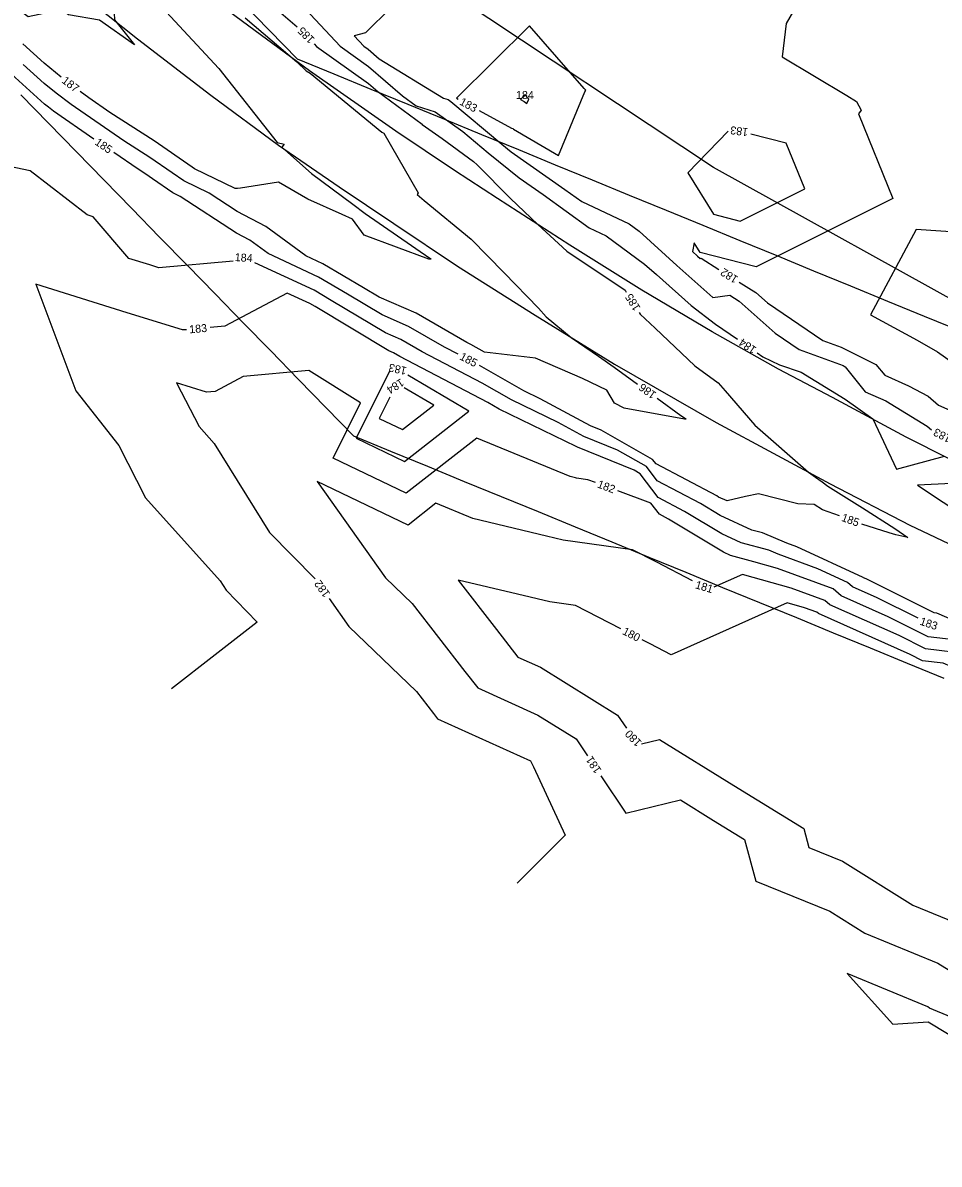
# Model space of a CAD drawing. Extents: x 2086416 to 2115205, y 575507 to 632762.
# Drawn here: x 2110459.9 to 2110689, y 581574.2 to 581859.5 of the extents above; entities that cross this region are included whole.
import ezdxf

# ---------------------------------------------------------------- set-up
doc = ezdxf.new("R2010")
doc.units = 0
for name, color, linetype in [('DTM Contours Major', 7, 'Continuous'), ('DTM Contours Major Text', 7, 'Continuous'), ('DTM Contours Minor', 7, 'Continuous'), ('DTM Contours Minor Text', 7, 'Continuous'), ('Exist Hydrographic FEMA Cross Section', 7, 'Continuous'), ('Exist Roads EOP', 7, 'Continuous'), ('Exist Vegetation Woods Line', 7, 'Continuous')]:
    doc.layers.add(name, color=color, linetype=linetype)

msp = doc.modelspace()

# ---------------------------------------------------------------- linework, layer by layer
at = {"layer": 'DTM Contours Major'}
for points in [[(2110457, 581927.88), (2110460.22, 581924.41), (2110465.69, 581919.7), (2110467.09, 581918.26), (2110471.2, 581912.48), (2110474.08, 581909.72), (2110478.74, 581904.23), (2110484.88, 581896.98), (2110489.67, 581891.41), (2110497.24, 581885.1), (2110503.54, 581879.8), (2110508.99, 581875.69), (2110517.48, 581867.91), (2110520.9, 581865), (2110528.46, 581858.48)], [(2110477.66, 581830.47), (2110467.52, 581837.44), (2110466.26, 581838.39), (2110465.28, 581839.19), (2110446.86, 581855.82), (2110445.45, 581856.9), (2110444.68, 581857.31), (2110425.22, 581874.31), (2110424.26, 581875.03), (2110421.59, 581877.72), (2110420.54, 581878.96), (2110417.81, 581883.75), (2110405.43, 581897.24), (2110404.4, 581897.68)], [(2110532.7, 581854.24), (2110533.29, 581853.61), (2110546.33, 581844.33), (2110548.63, 581842.34), (2110559.7, 581834.14), (2110559.75, 581834.13), (2110564.69, 581830.63), (2110572.56, 581824.83), (2110573.43, 581823.98), (2110581.79, 581815.57), (2110588.65, 581809.09), (2110593.79, 581804.33), (2110595.84, 581802.4), (2110610.44, 581792.71), (2110610.75, 581792.22)], [(2110568.71, 581776.67), (2110565.29, 581778.46), (2110556.33, 581783.64), (2110549.74, 581786.49), (2110541.03, 581791.71), (2110533.8, 581795.96), (2110521.17, 581801.83), (2110516.59, 581805.2), (2110513.26, 581806.95), (2110499.23, 581816.12), (2110497.37, 581817.02), (2110492.3, 581820.5), (2110490.63, 581821.65), (2110488.68, 581822.91), (2110482.6, 581827.08)], [(2110613.93, 581787.13), (2110614.2, 581786.7), (2110617.97, 581783.15), (2110627.86, 581773.78), (2110633.68, 581769.53), (2110635.48, 581767.5), (2110642.91, 581758.9), (2110656.28, 581747.21), (2110658.07, 581745.98), (2110659.68, 581744.77), (2110661.17, 581743.69), (2110669.84, 581738.28), (2110677.86, 581733.15), (2110681.1, 581730.87), (2110678.11, 581731.54), (2110676.51, 581732.02), (2110669.66, 581734.22)], [(2110664.02, 581736.26), (2110659.78, 581737.81), (2110657.7, 581739.14), (2110653.61, 581739.28), (2110643.82, 581741.77), (2110640.51, 581741.07), (2110635.97, 581739.99), (2110633.83, 581740.98), (2110633.38, 581741.25), (2110618.18, 581749.26), (2110617.34, 581750.37), (2110604.48, 581757.66), (2110601.81, 581758.74), (2110589.19, 581765.53), (2110585.16, 581767.49), (2110574.02, 581773.87)], [(2110609.4, 581708.01), (2110598.08, 581713.85), (2110591.61, 581714.75), (2110583.58, 581716.66), (2110568.72, 581720.2), (2110578.29, 581707.88), (2110583.65, 581700.97), (2110589.26, 581698.44), (2110608.58, 581686.48), (2110610.79, 581683.18)], [(2110706.28, 581691.93), (2110693.8, 581697.81), (2110690.01, 581699.43), (2110684.82, 581700.07), (2110681.7, 581701.62), (2110658.82, 581711.83), (2110658.38, 581712.2), (2110655.34, 581713.32), (2110650.98, 581714.55), (2110621.94, 581701.5), (2110616.68, 581704.25), (2110614.73, 581705.26)], [(2110614.54, 581679.26), (2110619.08, 581680.34), (2110637.66, 581668.88), (2110655.14, 581658.09), (2110656.42, 581653.38), (2110664.82, 581649.96), (2110682.42, 581638.95), (2110691.1, 581635.36), (2110698.64, 581630.7)]]:
    msp.add_lwpolyline(points, dxfattribs=at)
at = {"layer": 'DTM Contours Minor'}
for points in [[(2110672.37, 581932.97), (2110662.96, 581880.6), (2110650.69, 581859.37), (2110649.72, 581851), (2110665.85, 581841.38), (2110668.3, 581839.83), (2110669.46, 581837.68), (2110668.83, 581836.73), (2110677.42, 581815.61), (2110643.22, 581798.5), (2110629.19, 581802.12), (2110627.72, 581804.48), (2110627.29, 581802.33), (2110628.54, 581801.21), (2110629.18, 581800.63), (2110629.48, 581800.67), (2110633.9, 581797.89)], [(2110450.53, 581896.22), (2110460.85, 581885.58), (2110470.34, 581875.69), (2110478.68, 581867.9), (2110482.59, 581863.61), (2110482.79, 581860.24), (2110487.75, 581854.01), (2110479.08, 581860.14), (2110471.27, 581861.55), (2110469.42, 581862.78), (2110461.2, 581860.98), (2110453.09, 581866.98)], [(2110558.34, 581869.72), (2110545.52, 581856.99), (2110542.75, 581856.27), (2110545.16, 581853.69), (2110546.22, 581852.94), (2110548.99, 581850.55), (2110565.08, 581840.7), (2110566.2, 581840.35), (2110566.87, 581839.88), (2110579.59, 581829.15), (2110581.96, 581827.24), (2110595.34, 581817.89), (2110599.61, 581814.81), (2110611.44, 581809.26), (2110613.94, 581807.43), (2110623.41, 581798.89), (2110632.4, 581790.87), (2110636.67, 581791.41), (2110638.99, 581789.95), (2110647.93, 581781.91), (2110653.98, 581777.82), (2110665, 581773.88), (2110665.48, 581773.5), (2110670.48, 581767.29), (2110675.64, 581765.02), (2110686.01, 581758.67), (2110687.06, 581757.75)], [(2110529.31, 581864.26), (2110539.23, 581853.65), (2110546.28, 581848.63), (2110554.8, 581841.28), (2110558.25, 581838.73), (2110562.98, 581837.24), (2110569.88, 581832.35), (2110576.18, 581827.04), (2110583.95, 581820.79), (2110589.99, 581816.57), (2110601.5, 581808.27), (2110605.72, 581806.3), (2110615.34, 581799.22), (2110618.29, 581796.57), (2110626.94, 581788.84), (2110633.04, 581784.18), (2110638.55, 581780.4)], [(2110495.74, 581862.22), (2110508.87, 581848.12), (2110523.46, 581829.63), (2110525.22, 581829.21), (2110524.61, 581828.41), (2110532.08, 581821.86), (2110542.36, 581814.17), (2110545.49, 581811.81), (2110561.59, 581800.7), (2110561.76, 581800.58), (2110561.98, 581800.42), (2110561.7, 581800.45), (2110561.38, 581800.45), (2110545.25, 581806.45), (2110542.27, 581810.4), (2110539.71, 581811.6), (2110531.09, 581815.45), (2110523.77, 581819.71), (2110514.3, 581818.22), (2110513.57, 581818.12), (2110512.97, 581818.09), (2110502.82, 581823.01), (2110502.17, 581823.46), (2110492.67, 581829.99), (2110481.59, 581837.13), (2110476.34, 581840.73), (2110474.24, 581842.32)], [(2110515.46, 581860.72), (2110528.41, 581849.79), (2110530.67, 581847.54), (2110531.75, 581846.95), (2110549.59, 581832.22), (2110550.09, 581831.92), (2110558.68, 581817.04), (2110558.5, 581816.59), (2110559.05, 581816.07), (2110560.19, 581815.06), (2110571.99, 581805.45), (2110580.21, 581797), (2110588.8, 581788.18), (2110590.74, 581785.98), (2110597, 581780.84), (2110603.79, 581776.21), (2110607.72, 581773.43), (2110613.57, 581769.21)], [(2110600.23, 581843.07), (2110586.52, 581858.73), (2110568.37, 581840.76), (2110568.26, 581840.65), (2110568.7, 581840.41)], [(2110469.47, 581845.96), (2110465.2, 581849.45), (2110459.85, 581854.28)], [(2110618.43, 581765.7), (2110624.41, 581761.39), (2110625.53, 581760.59), (2110625.71, 581760.46), (2110625.57, 581760.44), (2110625.32, 581760.46), (2110610.18, 581763.16), (2110607.84, 581764.48), (2110605.89, 581767.69), (2110599.83, 581770.6), (2110588.05, 581775.67), (2110575.32, 581777.15), (2110571.92, 581779.1), (2110570.88, 581779.64), (2110558.23, 581786.95), (2110548.94, 581790.97), (2110545.08, 581793.28), (2110534.9, 581799.26), (2110530.6, 581801.26), (2110520.65, 581808.56), (2110513.43, 581812.38), (2110506.49, 581816.91), (2110500.09, 581820.02), (2110497.24, 581821.98), (2110491.65, 581825.82), (2110485.13, 581830.02), (2110471.93, 581839.08), (2110468.18, 581841.92), (2110465.24, 581844.32), (2110459.93, 581849.12)], [(2110573.98, 581837.56), (2110582.06, 581833.21), (2110582.34, 581833.06), (2110582.57, 581832.93), (2110593.83, 581826.33), (2110600.42, 581842.24), (2110600.59, 581842.66), (2110600.23, 581843.07)], [(2110585.45, 581841.47), (2110584.27, 581840.31), (2110585.18, 581839.82), (2110585.92, 581839.38), (2110586.35, 581840.44), (2110585.45, 581841.47)], [(2110636.25, 581832.4), (2110626.11, 581822.05), (2110632.59, 581811.67), (2110639.22, 581809.96)], [(2110639.22, 581809.96), (2110655.4, 581818.04), (2110650.75, 581829.46), (2110641.86, 581831.69)], [(2110512.45, 581799.94), (2110493.85, 581798.28), (2110491.61, 581798.98), (2110486.39, 581800.61), (2110477.44, 581810.98), (2110475.99, 581811.48), (2110461.73, 581822.53), (2110445.25, 581825.89), (2110436.87, 581830.21), (2110421.03, 581830.82), (2110422.59, 581804.61), (2110419.24, 581796.01), (2110417.96, 581786.65), (2110435.66, 581768.75), (2110437.3, 581769.68), (2110441.51, 581762.84), (2110427.74, 581762.65), (2110429.81, 581758.8)], [(2110699.21, 581806.73), (2110683.26, 581807.82), (2110671.77, 581786.48), (2110683.44, 581780.2), (2110688.54, 581777.3), (2110700.9, 581768.53), (2110709.47, 581765.13), (2110714.47, 581763.07)], [(2110695.32, 581708.96), (2110688.38, 581711.98), (2110687.7, 581712.06), (2110670.71, 581720.49), (2110670.08, 581720.77), (2110669.96, 581720.88), (2110653.37, 581728.55), (2110650.87, 581729.48), (2110644.8, 581731.99), (2110642.12, 581732.73), (2110634.23, 581736.4), (2110629.34, 581739.32), (2110618.45, 581745.06), (2110615.77, 581748.59), (2110608.58, 581752.66), (2110600.16, 581756.1), (2110593.72, 581759.57), (2110582.07, 581765.24), (2110574.71, 581769.45), (2110559.71, 581777.28), (2110554.42, 581780.33), (2110550.55, 581782.01), (2110536.98, 581790.14), (2110532.7, 581792.66), (2110517.86, 581799.55)], [(2110500.75, 581782.81), (2110499.83, 581782.73), (2110485.95, 581787.05), (2110463.09, 581794.19), (2110473.14, 581767.52), (2110483.87, 581753.84), (2110490.58, 581740.81), (2110509.23, 581720), (2110510.69, 581717.66), (2110518.48, 581709.68), (2110507.93, 581701.5), (2110497.05, 581693.06)], [(2110638.98, 581794.7), (2110643.14, 581792.08), (2110646.01, 581789.5), (2110659.86, 581780.13), (2110664.5, 581778.47), (2110673.17, 581774.14), (2110675.37, 581771.42), (2110681.32, 581768.8), (2110686.2, 581766.18), (2110688.77, 581763.93), (2110698.41, 581759.72)], [(2110683.75, 581710.67), (2110673.46, 581715.77), (2110667.27, 581718.53), (2110666.02, 581719.6), (2110658.64, 581723.02), (2110648.68, 581726.7), (2110646.35, 581727.67), (2110639.48, 581729.56), (2110634.63, 581731.81), (2110625.3, 581737.4), (2110618.73, 581740.86), (2110614.2, 581746.81), (2110612.68, 581747.67), (2110598.52, 581753.46), (2110598.25, 581753.6), (2110578.98, 581762.98), (2110576.1, 581764.63), (2110554.12, 581776.1), (2110552.52, 581777.02), (2110551.35, 581777.53), (2110532.93, 581788.57), (2110531.59, 581789.36), (2110525.98, 581791.96), (2110510.37, 581783.67), (2110506.73, 581783.34)], [(2110643.49, 581777), (2110644.91, 581776.03), (2110649.04, 581774.01), (2110654.46, 581772.18), (2110665.46, 581765.46), (2110672.35, 581760.51), (2110678.29, 581747.94), (2110690.29, 581751.21)], [(2110603.01, 581744.61), (2110601.15, 581745.31), (2110598.31, 581745.71), (2110598.02, 581745.77), (2110596.73, 581746.08), (2110573.36, 581755.71), (2110555.74, 581741.92), (2110537.44, 581750.71), (2110544.33, 581764.55), (2110531.39, 581772.62), (2110514.95, 581771.08), (2110507.97, 581767.37), (2110505.82, 581767.18), (2110498.31, 581769.52), (2110503.93, 581758.61), (2110507.74, 581754.35), (2110521.55, 581732.14), (2110532.92, 581720.5)], [(2110551.55, 581772.41), (2110543.21, 581755.67), (2110555.29, 581749.87)], [(2110555.29, 581749.87), (2110571.37, 581762.46), (2110556.13, 581771.4)], [(2110551.65, 581765.96), (2110548.99, 581760.63), (2110554.83, 581757.82)], [(2110554.83, 581757.82), (2110562.62, 581763.92), (2110555.24, 581768.24)], [(2110627.31, 581720), (2110618.35, 581724.7), (2110612.34, 581727.81), (2110594.96, 581730.23), (2110590.8, 581731.21), (2110572.39, 581735.61), (2110563.15, 581739.41), (2110556.19, 581733.96), (2110533.5, 581744.86), (2110550.52, 581720.81), (2110557.19, 581714.38), (2110570.41, 581697.37), (2110573.61, 581693.25), (2110588.65, 581686.44), (2110598.2, 581680.53), (2110601.06, 581676.27)], [(2110695.55, 581744.5), (2110683.59, 581743.96), (2110696.4, 581735.45)], [(2110694.89, 581704.99), (2110686.26, 581706.07), (2110676.21, 581711.05), (2110664.45, 581716.3), (2110662.47, 581718.01), (2110648.59, 581723.13), (2110642.65, 581724.79), (2110636.84, 581726.39), (2110635.03, 581727.23), (2110621.26, 581735.48), (2110619.01, 581736.67), (2110616.91, 581739.41), (2110608.63, 581742.51)], [(2110696.5, 581701.71), (2110685.54, 581703.07), (2110678.96, 581706.34), (2110661.63, 581714.06), (2110660.42, 581715.1), (2110651.96, 581718.23), (2110639.81, 581721.63), (2110632.66, 581718.42)], [(2110536.42, 581715.62), (2110541.37, 581708.61), (2110558.26, 581692.36), (2110562.53, 581686.86), (2110563.56, 581685.53), (2110586.82, 581675), (2110587.51, 581673.53), (2110595.49, 581656.49), (2110583.43, 581644.45)], [(2110604.39, 581671.28), (2110610.61, 581661.99), (2110624.31, 581665.25), (2110632.56, 581660.16), (2110640.32, 581655.37), (2110643.15, 581644.99), (2110661.66, 581637.44), (2110670.37, 581631.99), (2110688.6, 581624.45), (2110697.54, 581618.92), (2110715.51, 581611.4), (2110724.37, 581605.97), (2110742.09, 581598.48), (2110752.98, 581596.4), (2110770.33, 581589.17), (2110775.18, 581586.24)], [(2110742.87, 581589.81), (2110740.96, 581590.18), (2110714.65, 581601.3), (2110713.6, 581601.94), (2110686.58, 581613.24), (2110686.1, 581613.54), (2110665.95, 581621.88), (2110677.38, 581609.19), (2110686.18, 581609.76), (2110710, 581595.5), (2110714.28, 581597.88), (2110733.49, 581588.34), (2110739.88, 581585.59), (2110744.53, 581584.59), (2110766.06, 581574.38), (2110767.08, 581574.21)]]:
    msp.add_lwpolyline(points, dxfattribs=at)
at = {"layer": 'Exist Hydrographic FEMA Cross Section'}
for points in [[(2110694.56, 581782.32), (2110685.33, 581786.1), (2110676.11, 581789.89), (2110666.89, 581793.68), (2110657.66, 581797.46), (2110648.43, 581801.24), (2110639.21, 581805.03), (2110629.98, 581808.82), (2110620.76, 581812.6), (2110611.53, 581816.38), (2110602.31, 581820.17), (2110593.08, 581823.95), (2110583.86, 581827.74), (2110574.63, 581831.52), (2110565.41, 581835.31), (2110556.18, 581839.09), (2110546.96, 581842.88), (2110537.73, 581846.66), (2110528.51, 581850.45), (2110521.57, 581857.56), (2110514.63, 581864.67)], [(2110690.26, 581695.61), (2110681.04, 581699.39), (2110671.81, 581703.18), (2110662.58, 581706.96), (2110653.36, 581710.75), (2110644.14, 581714.53), (2110634.91, 581718.32), (2110625.68, 581722.1), (2110616.46, 581725.89), (2110607.23, 581729.67), (2110598.01, 581733.46), (2110588.78, 581737.24), (2110579.56, 581741.02), (2110570.33, 581744.81), (2110561.11, 581748.6), (2110551.88, 581752.38), (2110542.66, 581756.16), (2110535.72, 581763.28), (2110528.78, 581770.39), (2110521.84, 581777.5), (2110514.9, 581784.61), (2110507.96, 581791.73), (2110501.02, 581798.84), (2110494.08, 581805.95), (2110487.15, 581813.06), (2110480.2, 581820.18), (2110473.27, 581827.28), (2110466.33, 581834.4), (2110459.39, 581841.51)]]:
    msp.add_lwpolyline(points, dxfattribs=at)
at = {"layer": 'Exist Roads EOP'}
for points in [[(2110859.62, 581680.71), (2110839.18, 581687.57), (2110822.39, 581693.78), (2110804.41, 581700.49), (2110791.36, 581705.43), (2110777.14, 581711.28), (2110760, 581718.68), (2110741.24, 581726.89), (2110721.85, 581735.85), (2110702.22, 581745.1), (2110680.73, 581755.98), (2110662.27, 581765.85), (2110648.84, 581772.92), (2110632.22, 581782.31), (2110614.63, 581792.7), (2110596.64, 581803.91), (2110578.53, 581815.64), (2110567.83, 581822.57), (2110553.15, 581832.42), (2110531.54, 581847.48), (2110510.05, 581863.33), (2110489.25, 581879.31), (2110463.15, 581900.73), (2110445.32, 581916.19)], [(2110454.4, 581883.19), (2110469.83, 581870.54), (2110488.57, 581855.49), (2110506.88, 581841.42), (2110523.82, 581828.96), (2110539, 581818.5), (2110552.64, 581809.38), (2110568.55, 581798.72), (2110587.98, 581786.4), (2110607.77, 581774.2), (2110633.24, 581759.62), (2110661.71, 581744.29), (2110681.63, 581733.96), (2110708.85, 581721.01), (2110734.15, 581708.98), (2110768.01, 581694.36), (2110797.99, 581682.47), (2110825.02, 581672.22), (2110850.72, 581663.8), (2110872.12, 581657.17), (2110892.09, 581651.25), (2110910.76, 581646.06), (2110929.15, 581641.61)]]:
    msp.add_lwpolyline(points, dxfattribs=at)
at = {"layer": 'Exist Vegetation Woods Line'}
msp.add_lwpolyline([(2111059.79, 581657.65), (2110968.73, 581672.25), (2110864.06, 581705.25), (2110784.73, 581740.8), (2110702.3, 581784.67), (2110632.54, 581823.34), (2110568.48, 581865.95), (2110498.27, 581913.79), (2110441.66, 581966.78), (2110387.94, 582016.39), (2110334.43, 582063.69), (2110284.48, 582120.87)], dxfattribs=at)

# ---------------------------------------------------------------- texts
at = {"layer": 'DTM Contours Major Text'}
for s, rotation, p in [('185', 135.0298, (2110532.97, 581855.53)), ('185', 325.5233, (2110477.69, 581829.24)), ('185', 122.01, (2110614.39, 581788.28)), ('185', 332.1435, (2110568.9, 581775.47)), ('185', 340.1435, (2110664.36, 581735.06)), ('180', 332.7022, (2110609.59, 581706.79)), ('180', 133.7488, (2110614.75, 581679.73))]:
    msp.add_text(s, height=2, rotation=rotation, dxfattribs=at).set_placement(p)
at = {"layer": 'DTM Contours Minor Text'}
for s, rotation, p in [('187', 322.626, (2110469.43, 581844.71)), ('183', 331.6951, (2110568.87, 581839.18)), ('183', 172.7596, (2110641.33, 581833.12)), ('184', 355.9402, (2110512.8, 581799.98)), ('182', 147.8244, (2110638.9, 581795.93)), ('183', 5.085, (2110501.56, 581781.88)), ('184', 145.5161, (2110643.46, 581778.24)), ('183', 167.476, (2110555.98, 581773.4)), ('184', 212.3802, (2110554.37, 581770.71)), ('186', 144.1901, (2110618.43, 581766.94)), ('183', 152.3918, (2110692.18, 581756.2)), ('182', 339.4999, (2110603.33, 581743.42)), ('182', 125.6497, (2110536.82, 581716.81)), ('181', 343.4853, (2110627.83, 581718.2)), ('183', 341.2986, (2110683.96, 581709.12)), ('181', 123.788, (2110604.63, 581672.72))]:
    msp.add_text(s, height=2, rotation=rotation, dxfattribs=at).set_placement(p)
msp.add_text('184', height=2, dxfattribs=at).set_placement((2110583.17, 581840.47))

doc.saveas('drawing.dxf')
